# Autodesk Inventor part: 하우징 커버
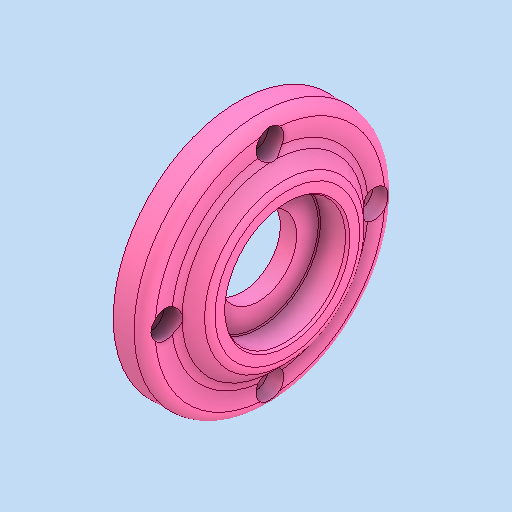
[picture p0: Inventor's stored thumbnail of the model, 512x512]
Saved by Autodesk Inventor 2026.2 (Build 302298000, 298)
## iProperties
Created: 2026-01
Part Number: 하우징 커버
Material: 알루미늄 6061
Document SubType Name: Modeling
Designer: PC2-07
Density: 2.7 g/cm^3
Appearance: 기본값
Author: jhkim
Sending System: Autodesk Inventor 2026
Preprocessor: ST-DEVELOPER v20.1
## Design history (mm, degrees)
feature "솔리드1"
node "솔리드2"
